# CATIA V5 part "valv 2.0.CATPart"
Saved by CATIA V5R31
Part number: valv 2.0
Bounding box of the stored display mesh (mm): x -49.5 to 49.5, y -54 to 69, z -5 to 5
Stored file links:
  C:\Users\189361\Desktop\piezas del comedero\piezas del comedero\valv 2.0.CATPart
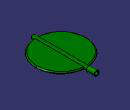
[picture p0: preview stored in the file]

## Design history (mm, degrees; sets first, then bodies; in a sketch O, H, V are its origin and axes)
Body1 (main body)
  Sketch1 on xy-plane, origin (0, 0, 0), H (1, 0, 0), V (0, 1, 0)
    circle A1 centre (0, 0) radius 49.5
    radius A1 = 49.5
  Pad1: profile Sketch1, direction (0, 0, 1), length 2, opposite side length 2
  Fillet1: radius 2, on edge [face of Pad1 from Sketch1.A1 | end face of Pad1]; edge [start face of Pad1 | face of Pad1 from Sketch1.A1]
  Sketch2 on zx-plane, origin (0, 0, 0), H (-1, 0, 0), V (0, 0, 1)
    circle A1 centre (0, 0) radius 4
    radius A1 = 4
  Pad2: profile Sketch2, direction (0, 1, 0), length 54, opposite side length 54
  Sketch3 on end face of Pad2, origin (0, 54, 0), H (-1, 0, 0), V (0, 0, 1)
    circle A1 centre (0, 0) radius 5
    circle A2 centre (0, 0) radius 3.2
    point P1 (0, 0)
    radius A1 = 5
    radius A2 = 3.2
    coincidence: P1 V, P1 O
  Pad3: profile Sketch3, direction (0, 1, 0), length 15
